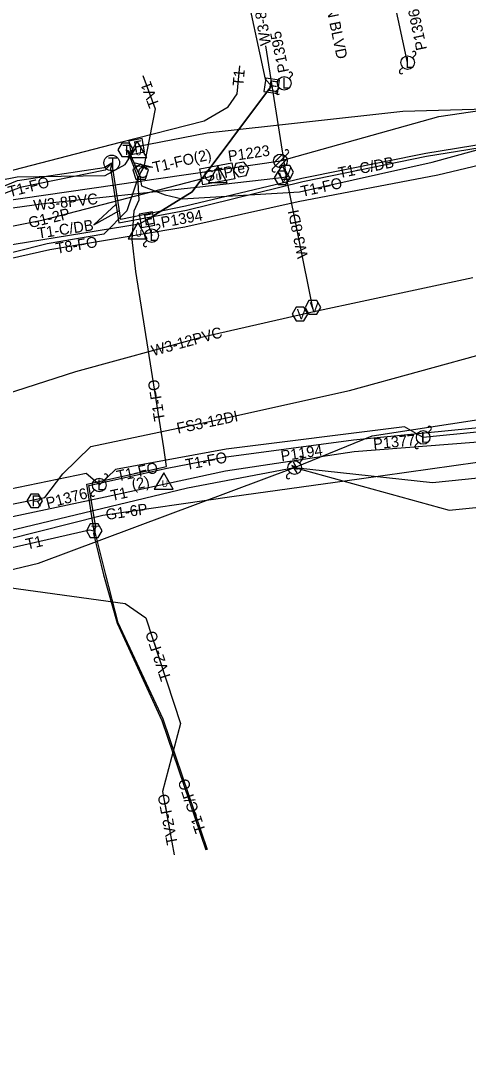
# Model space of a CAD drawing. Extents: x 2336688 to 2352634, y 362473 to 369571.
# Drawn here: x 2351731.6 to 2351896.3, y 368636.2 to 369013.7 of the extents above; entities that cross this region are included whole.
import ezdxf

# ---------------------------------------------------------------- set-up
doc = ezdxf.new("R2010")
doc.units = 0
for name, color, linetype in [('RD_EX_DV_TX_Prop', 7, 'Continuous'), ('RD_EX_RW', 7, 'Continuous'), ('RD_EX_RW_TX', 7, 'Continuous'), ('RD_HC_CL_Rel', 7, 'Continuous'), ('RD_HC_Data_Tic', 7, 'Continuous'), ('RD_PD_CstnLmt', 7, 'Continuous'), ('RD_PD_Final_TrvlWay', 7, 'Continuous'), ('RD_PD_PatLn2', 7, 'Continuous'), ('RD_PD_PatLn3', 7, 'Continuous'), ('RD_SHT_ShtClip', 7, 'Continuous'), ('RD_Sketch1', 7, 'Continuous'), ('RD_Sketch2', 7, 'Continuous'), ('RD_Sketch5', 7, 'Continuous'), ('RD_TX_Misc1', 7, 'Continuous')]:
    doc.layers.add(name, color=color, linetype=linetype)

msp = doc.modelspace()

# ---------------------------------------------------------------- linework, layer by layer
at = {"layer": 'RD_EX_RW'}
for p, q in [((2351780.21, 368959.6), (2351773.09, 368960.29)), ((2351780.21, 368959.6), (2351773.27, 368961.33)), ((2351758.51, 368938.6), (2351766.67, 368946.17)), ((2351758.47, 368938.59), (2351767.94, 368943.79))]:
    msp.add_line(p, q, dxfattribs=at)
at = {"layer": 'RD_EX_RW_TX'}
for points in [[(2351674.66, 368979.28), (2351676.95, 368964.93), (2351681.61, 368946.8), (2351685.81, 368947.48), (2351730.37, 368956.23), (2351762.74, 368956.69), (2351770.03, 368960.75), (2351774.28, 368967.37), (2351800.15, 368972.4), (2351872.17, 368980.36), (2351937.74, 368982.19), (2351987.22, 368989.17), (2352041.91, 368999.4), (2352065.6, 369002.37), (2352089.73, 369004.61), (2352102.55, 369007.6), (2352102.58, 369015.62), (2352100.79, 369043.46)], [(2352338.07, 368997.32), (2352288.54, 369002.61), (2352238.52, 369006.32), (2352188.44, 369009.03), (2352146.1, 369006.66), (2352112.83, 369007.85), (2352101.04, 369009.02), (2352100.18, 369013.02), (2352099.24, 369013.18), (2352099.24, 369013.18), (2352097.56, 369004.44), (2352066.15, 368999.94), (2352042.65, 368996), (2351987.9, 368984.55), (2351939.24, 368974.38), (2351880.64, 368964.81), (2351835.05, 368955.54), (2351792.2, 368945.42), (2351768.45, 368940.51), (2351765.56, 368959.31), (2351765.09, 368961.33)], [(2351441.13, 368877.68), (2351493.72, 368892.16), (2351542.92, 368904.09), (2351587.97, 368921.36), (2351612.24, 368928.51), (2351643.03, 368939.04), (2351685.22, 368949.09), (2351729.04, 368958.84), (2351768.34, 368969.01), (2351799.1, 368976.84), (2351807.9, 368981.96), (2351811.24, 368986.71), (2351812.17, 368997.01)], [(2351776.48, 368993.53), (2351781.05, 368981.28), (2351776.85, 368959.84), (2351775.71, 368957.81), (2351774.05, 368953.89), (2351770.61, 368943.72), (2351762.16, 368935.08), (2351741.35, 368931.51), (2351693.7, 368919.57), (2351644.17, 368909.19), (2351595.95, 368896.32), (2351580.02, 368891.2), (2351548.35, 368884.52), (2351499.06, 368872), (2351450.2, 368859.78)], [(2351758.66, 368825.96), (2351758.44, 368827.26), (2351755.96, 368843.15), (2351785.24, 368849.63), (2351784.29, 368856.52), (2351773.91, 368921.34), (2351772.63, 368933.13), (2351773.4, 368943.66), (2351775.18, 368947.68), (2351774.66, 368956.23), (2351771, 368965.69), (2351770.23, 368966.13), (2351771.27, 368965.86), (2351775.42, 368956.47), (2351776.04, 368952.93), (2351784.75, 368949.58), (2351790.96, 368948.12), (2351834.08, 368950.74), (2351882.96, 368961.6), (2351938.79, 368976.9)], [(2351450, 368860.64), (2351498.06, 368873.82), (2351548.09, 368885.57), (2351595.68, 368897.58), (2351616.34, 368903.53), (2351642.63, 368914.43), (2351689.81, 368938.15), (2351730.46, 368954.84), (2351762.28, 368959.7), (2351765.09, 368961.33), (2351764.64, 368959.22), (2351767.74, 368939.28), (2351792.58, 368943.98), (2351835.36, 368954.52), (2351880.81, 368963.77), (2351939.3, 368973.2)], [(2351026.67, 368705.73), (2351072.69, 368726.31), (2351095.34, 368740.06), (2351116.22, 368749.97), (2351165.51, 368767.17), (2351212.21, 368781.21), (2351311.35, 368807.4), (2351356.55, 368822.99), (2351403.13, 368840.09), (2351451.54, 368852.43), (2351499.93, 368866.02), (2351548.68, 368876.43), (2351597.38, 368889.51), (2351644.05, 368904.92), (2351693.91, 368918.56), (2351742.3, 368929.46), (2351791.99, 368937.8), (2351833.59, 368947.12), (2351885, 368956.88), (2351939.56, 368969.89)], [(2351765.09, 368961.33), (2351762.65, 368958.7), (2351731.46, 368952.33), (2351690.92, 368936.8), (2351644.39, 368912.81), (2351617.15, 368901.31), (2351597.28, 368893.86), (2351548.04, 368883.26), (2351498.82, 368871.39), (2351450.63, 368858.65), (2351402.34, 368844.85), (2351353.62, 368832.17), (2351306.23, 368821.59), (2351280.49, 368815.25), (2351211.24, 368794.97), (2351186.06, 368787.7), (2351186.43, 368794.28), (2351186.89, 368796.09), (2351185.08, 368794.48), (2351153.67, 368786.02), (2351107.67, 368770.53), (2351057.77, 368748.3), (2351012.48, 368735.27)], [(2351800.26, 368708.59), (2351783.98, 368756.59), (2351767.48, 368792.11), (2351762.88, 368809.69), (2351759.04, 368825.42), (2351758.66, 368825.96), (2351759.26, 368827.23), (2351756.66, 368842.63), (2351785.44, 368848.99), (2351806.34, 368852.99), (2351854.03, 368859.38), (2351906.18, 368864.55), (2351953.78, 368869.16), (2351999.38, 368874.93), (2352002.29, 368863.43), (2352001.55, 368861.67), (2352003.47, 368859.64), (2352009.35, 368840.16), (2352015.45, 368822.2), (2352011.56, 368815.85), (2352019.33, 368768.13), (2352023.49, 368743.71)], [(2351356.36, 368718.44), (2351351.37, 368734.97), (2351351.07, 368736.27), (2351352.08, 368735.83), (2351354.55, 368734.64), (2351363.44, 368738.12), (2351379.73, 368744.54), (2351398.33, 368751.76), (2351424.73, 368759.16), (2351470.85, 368771.57), (2351519.59, 368782.94), (2351559.62, 368792.7), (2351576.11, 368797.45), (2351601.1, 368804.55), (2351618.26, 368808.83), (2351664.35, 368818.5), (2351712.26, 368827.78), (2351760.99, 368838.04), (2351806.87, 368848.05), (2351854.2, 368855.12), (2351907.65, 368859.27)], [(2351469.79, 368774.45), (2351518.56, 368788.63), (2351559.06, 368797.29), (2351582.72, 368800.31), (2351584.07, 368794.92), (2351586.12, 368789.37), (2351586.25, 368788.52), (2351587.94, 368791.42), (2351594.9, 368792.63), (2351620.36, 368798.87), (2351634.16, 368804.06), (2351665.64, 368810.12), (2351714.33, 368816.59), (2351756.9, 368826.27), (2351758.66, 368825.96), (2351758.35, 368824.95), (2351762.12, 368809.74), (2351767.08, 368791.96), (2351783.55, 368756.14), (2351799.72, 368708.59)], [(2351637.62, 368802.44), (2351638.61, 368802.8), (2351648.75, 368802.95), (2351666.69, 368806.19), (2351717.35, 368806.44), (2351770.06, 368799.18), (2351777.6, 368793.92), (2351790.36, 368754.99), (2351783.74, 368729.96), (2351788.08, 368706.76)]]:
    msp.add_lwpolyline(points, dxfattribs=at)
for points in [[(2351773.12, 368966.13), (2351771.67, 368968.63), (2351768.79, 368968.63), (2351767.34, 368966.13), (2351768.79, 368963.63), (2351771.67, 368963.63)], [(2351776.29, 368970.28), (2351771.37, 368969.38), (2351772.27, 368964.46), (2351777.19, 368965.36)], [(2351775.71, 368960.81), (2351772.86, 368958.73), (2351773.95, 368955.38), (2351777.48, 368955.38), (2351778.57, 368958.73)], [(2351761.54, 368825.96), (2351760.1, 368828.46), (2351757.21, 368828.46), (2351755.77, 368825.96), (2351757.21, 368823.46), (2351760.1, 368823.46)]]:
    msp.add_lwpolyline(points, close=True, dxfattribs=at)
msp.add_circle((2351765.09, 368961.33), 2.89, dxfattribs=at)
at = {"layer": 'RD_HC_CL_Rel'}
for points in [[(2351211.87, 369060.2), (2351223.48, 369007.05), (2351235.68, 368951.97), (2351248.3, 368899.28), (2351256.86, 368864.38), (2351258.4, 368860.79), (2351267.06, 368853.06), (2351279.19, 368842.1), (2351287.59, 368836.67), (2351300.9, 368835.62), (2351301.79, 368834.14), (2351303.04, 368833.64), (2351320.88, 368837.27), (2351336.77, 368841.59), (2351351.45, 368846.05), (2351396.57, 368859.65), (2351447.03, 368875.53), (2351494.07, 368886.58), (2351543.46, 368901.18), (2351588.65, 368910.33), (2351641.69, 368920.56), (2351691.88, 368930.79), (2351740.06, 368940.33), (2351801.74, 368956.51)], [(2351470.14, 368766.16), (2351521.03, 368777.02), (2351560.63, 368787.9), (2351594.48, 368794.14), (2351619.97, 368801.96), (2351648.53, 368809.83), (2351665.14, 368813.04), (2351714.69, 368819.75), (2351761.78, 368831.73), (2351809.21, 368838.57), (2351856.12, 368845.07), (2351908.31, 368852.47)]]:
    msp.add_lwpolyline(points, dxfattribs=at)
for points in [[(2351810.38, 368955.41), (2351798.58, 368953.2), (2351797.48, 368959.1), (2351809.27, 368961.31)], [(2351815.5, 368959.42), (2351813.62, 368961.61), (2351810.78, 368961.08), (2351809.83, 368958.36), (2351811.7, 368956.17), (2351814.54, 368956.7)]]:
    msp.add_lwpolyline(points, close=True, dxfattribs=at)
at = {"layer": 'RD_HC_Data_Tic'}
for p, q in [((2351875.67, 369000), (2351876.74, 369001.06)), ((2351871.08, 368995.41), (2351872.14, 368996.47)), ((2351830.29, 368992.39), (2351831.35, 368993.46)), ((2351825.69, 368987.8), (2351826.75, 368988.86)), ((2351824.7, 368961.41), (2351827.76, 368964.47)), ((2351825.35, 368960.29), (2351828.88, 368963.82)), ((2351828.88, 368963.82), (2351829.95, 368964.88)), ((2351824.29, 368959.23), (2351825.35, 368960.29)), ((2351826.47, 368959.64), (2351829.53, 368962.7)), ((2351781.57, 368936.33), (2351782.63, 368937.39)), ((2351776.97, 368931.74), (2351778.03, 368932.8)), ((2351881.38, 368862.06), (2351882.44, 368863.12)), ((2351876.78, 368857.47), (2351877.84, 368858.53)), ((2351834.12, 368850.99), (2351835.18, 368852.05)), ((2351829.52, 368846.4), (2351830.58, 368847.46)), ((2351762.27, 368844.56), (2351763.33, 368845.62)), ((2351757.67, 368839.96), (2351758.73, 368841.02))]:
    msp.add_line(p, q, dxfattribs=at)
msp.add_lwpolyline([(2351831.96, 368851.23), (2351832.78, 368849.22), (2351831.33, 368850.02), (2351833.2, 368847.34), (2351833.2, 368847.34), (2351832, 368849.43), (2351833.38, 368848.63)], close=True, dxfattribs=at)
for centre in [(2351873.91, 368998.24), (2351828.52, 368990.63), (2351827.12, 368962.06), (2351779.8, 368934.57), (2351879.61, 368860.3), (2351832.35, 368849.22), (2351760.5, 368842.79)]:
    msp.add_circle(centre, 2.5, dxfattribs=at)
for centre, start, end in [((2351876.21, 369001.59), 315, 135), ((2351830.82, 368993.99), 315, 135), ((2351871.61, 368994.88), 135, 315), ((2351826.22, 368987.27), 135, 315), ((2351829.42, 368965.41), 315, 135), ((2351824.82, 368958.7), 135, 315), ((2351782.1, 368937.92), 315, 135), ((2351777.5, 368931.21), 135, 315), ((2351881.91, 368863.65), 315, 135), ((2351877.31, 368856.94), 135, 315), ((2351834.65, 368852.58), 315, 135), ((2351762.8, 368846.15), 315, 135), ((2351830.05, 368845.87), 135, 315), ((2351758.2, 368839.43), 135, 315)]:
    msp.add_arc(centre, 0.75, start, end, dxfattribs=at)
at = {"layer": 'RD_PD_Final_TrvlWay'}
for p, q in [((2351873.91, 368998.24), (2351857.57, 369073.04)), ((2351778.05, 368940.44), (2351779.8, 368934.57))]:
    msp.add_line(p, q, dxfattribs=at)
for points in [[(2351813.53, 369029.36), (2351821.49, 368992.14), (2351823.9, 368989.67), (2351794.62, 368950.67), (2351778.05, 368940.44), (2351775.15, 368938.78), (2351642.49, 368917.24), (2351514.5, 368883.56), (2351514.77, 368877.23), (2351511.62, 368882.8), (2351407.12, 368855.31), (2351405.59, 368848.58), (2351402.3, 368851.72), (2351332.34, 368833.32), (2351331.07, 368827.87)], [(2351778.05, 368940.44), (2351794.62, 368950.67), (2351823.9, 368989.67)], [(2351962.19, 368868.54), (2351879.61, 368860.3), (2351872.73, 368864.24), (2351807.16, 368856.02), (2351766.5, 368848.48), (2351760.54, 368842.85), (2351755.71, 368847.01), (2351656.05, 368826.47), (2351653.74, 368820.38), (2351649.2, 368824.53), (2351583.65, 368809.05), (2351587.65, 368792.13), (2351587.61, 368789.27), (2351586.29, 368791.8), (2351582.29, 368808.73), (2351542.35, 368799.3), (2351537.51, 368798.37), (2351536.49, 368793.38), (2351533.02, 368797.4), (2351459.1, 368778.67), (2351456.43, 368773.13), (2351451.34, 368775.83), (2351353, 368749.17), (2351345.06, 368741.32)]]:
    msp.add_lwpolyline(points, dxfattribs=at)
for points in [[(2351826.74, 368991.78), (2351821.8, 368992.51), (2351821.06, 368987.57), (2351826.01, 368986.83)], [(2351780.05, 368943.35), (2351775.14, 368942.44), (2351776.05, 368937.53), (2351780.96, 368938.44)]]:
    msp.add_lwpolyline(points, close=True, dxfattribs=at)
at = {"layer": 'RD_PD_PatLn3'}
for points in [[(2351774.5, 368969.36), (2351771.04, 368963.36), (2351777.97, 368963.36)], [(2351804.1, 368960.17), (2351800.64, 368954.17), (2351807.57, 368954.17)], [(2351774.64, 368939.41), (2351771.18, 368933.41), (2351778.11, 368933.41)], [(2351784.23, 368847.28), (2351780.76, 368841.28), (2351787.69, 368841.28)]]:
    msp.add_lwpolyline(points, close=True, dxfattribs=at)
at = {"layer": 'RD_SHT_ShtClip'}
msp.add_line((2351572.13, 368925.03), (2351827.12, 368962.06), dxfattribs=at)
for points in [[(2351827.12, 368962.06), (2351885.36, 368978.36), (2352011.84, 368996.99), (2352072.58, 368998.19)], [(2351832.35, 368849.22), (2351860.91, 368860.88), (2352060.94, 368891.58), (2352091.68, 368889.02)], [(2351832.35, 368849.22), (2351889.18, 368833.54), (2352180.82, 368862.57), (2352233.45, 368889.14)], [(2351832.35, 368849.22), (2351883.04, 368843.68), (2352056.96, 368861.54), (2352105.46, 368877.27)], [(2351439.98, 368755.4), (2351540.29, 368766.59), (2351738.13, 368814.04), (2351832.35, 368849.22)], [(2351637.62, 368802.44), (2351676.06, 368813.68), (2351793, 368841.77), (2351832.35, 368849.22)]]:
    msp.add_lwpolyline(points, dxfattribs=at)
at = {"layer": 'RD_Sketch2'}
for points in [[(2351839.37, 368906.5), (2351838.84, 368909.14), (2351829.3, 368956.12), (2351829.09, 368957.89), (2351821.73, 369004.47)], [(2351829.3, 368956.12), (2351825.48, 368955.65), (2351796.45, 368952.27), (2351741.12, 368946.36), (2351687.12, 368939), (2351639.33, 368929.45), (2351588.67, 368920.67), (2351539, 368909.06), (2351489.27, 368896.27), (2351440.12, 368880.97), (2351434.75, 368879.34), (2351397.29, 368866.24), (2351394.12, 368865.24), (2351393.38, 368867.94), (2351392.71, 368869.71)], [(2351897.87, 368918.99), (2351839.37, 368906.5), (2351797.47, 368896.96), (2351751.8, 368884.48), (2351707.52, 368870.2), (2351656.24, 368856.32), (2351608.11, 368843.77), (2351558.65, 368832.09), (2351508.67, 368819.53), (2351459.49, 368806.33), (2351412.81, 368793.12), (2351368.32, 368777.82), (2351320.48, 368761.6), (2351291.49, 368752.07), (2351283.21, 368749.13), (2351230.34, 368719.64), (2351184.82, 368699.7), (2351136.28, 368683.67), (2351113.69, 368676.51), (2351093.58, 368668.35), (2351042.86, 368655.18), (2350995.25, 368636.19)]]:
    msp.add_lwpolyline(points, dxfattribs=at)
for points in [[(2351831.98, 368957.89), (2351830.53, 368960.39), (2351827.65, 368960.39), (2351826.2, 368957.89), (2351827.65, 368955.39), (2351830.53, 368955.39)], [(2351830.61, 368955.85), (2351829.17, 368958.35), (2351826.28, 368958.35), (2351824.84, 368955.85), (2351826.28, 368953.35), (2351829.17, 368953.35)], [(2351841.96, 368908.17), (2351840.52, 368910.67), (2351837.63, 368910.67), (2351836.19, 368908.17), (2351837.63, 368905.67), (2351840.52, 368905.67)], [(2351837.21, 368905.69), (2351835.77, 368908.19), (2351832.88, 368908.19), (2351831.44, 368905.69), (2351832.88, 368903.19), (2351835.77, 368903.19)]]:
    msp.add_lwpolyline(points, close=True, dxfattribs=at)
at = {"layer": 'RD_Sketch5'}
msp.add_lwpolyline([(2351470.05, 368773.88), (2351518.77, 368787.72), (2351559.13, 368796.23), (2351617.79, 368811.57), (2351663.83, 368820.09), (2351711.27, 368832.32), (2351740.53, 368838.18), (2351747.1, 368846.93), (2351757.38, 368857), (2351803.33, 368866.61), (2351852.53, 368877.54), (2351904.23, 368891.75)], dxfattribs=at)
msp.add_lwpolyline([(2351739.67, 368836.98), (2351738.22, 368839.48), (2351735.34, 368839.48), (2351733.89, 368836.98), (2351735.34, 368834.47), (2351738.22, 368834.47)], close=True, dxfattribs=at)

# ---------------------------------------------------------------- texts
at = {"layer": 'RD_EX_DV_TX_Prop'}
for s, rotation, p in [('P1396', 101.6792, (2351881.04, 369003.19)), ('P1395', 101.6792, (2351830.31, 368994.96)), ('P1223', 8.2617, (2351808.15, 368961.8)), ('P1394', 10.334, (2351783.56, 368937.44)), ('P1377', 5.6602, (2351861.45, 368855.9)), ('P1194', 8.4903, (2351827.55, 368851.47)), ('P1376', 14.3887, (2351741.49, 368834.13))]:
    msp.add_text(s, height=4, rotation=rotation, dxfattribs=at).set_placement(p)
at = {"layer": 'RD_EX_RW'}
for s, rotation, p in [('T1', 84.8472, (2351813.49, 368989.4)), ('TV1', 110.4499, (2351782.72, 368982.52)), ('T1-FO(2)', 13.1603, (2351780.67, 368957.66)), ('T1-C/DB', 11.4971, (2351848.8, 368955.65)), ('T1-FO', 14.5402, (2351727.53, 368948.67)), ('T1-FO', 12.5252, (2351835.1, 368948.81)), ('T1-C/DB', 8.7436, (2351738.08, 368933.43)), ('T8-FO', 9.5373, (2351744.87, 368927.86)), ('T1-FO', 99.0986, (2351784.7, 368866.63)), ('T1-FO', 10.5947, (2351792.58, 368848.32)), ('T1-FO', 12.4764, (2351767.36, 368844.06)), ('(2)', 12.4764, (2351772.91, 368840.9)), ('T1', 12.3146, (2351765.13, 368836.89)), ('T1', 12.81, (2351733.96, 368819)), ('TV2-FO', 108.1342, (2351787.06, 368771.48)), ('T1-C/FO', 108.7769, (2351799.76, 368715.49)), ('TV2-FO', 100.5767, (2351789.37, 368710.73))]:
    msp.add_text(s, height=4, rotation=rotation, dxfattribs=at).set_placement(p)
at = {"layer": 'RD_EX_RW_TX'}
for height, p in [(3.75, (2351769.02, 368964.26)), (4.12, (2351763.76, 368959.27)), (3.75, (2351757.45, 368824.08))]:
    msp.add_text('T', height=height, dxfattribs=at).set_placement(p)
for s, rotation, p in [('F', 10.334, (2351773.52, 368965.2)), ('C', 360, (2351774.49, 368955.81))]:
    msp.add_text(s, height=4, rotation=rotation, dxfattribs=at).set_placement(p)
at = {"layer": 'RD_HC_CL_Rel'}
for s, height, p in [('GTP', 4, (2351799.31, 368954.35)), ('e', 3.75, (2351811.62, 368957.27))]:
    msp.add_text(s, height=height, rotation=10.6138, dxfattribs=at).set_placement(p)
at = {"layer": 'RD_HC_Data_Tic'}
for p in [(2351873.1, 368996.3), (2351827.71, 368988.69), (2351778.99, 368932.63), (2351878.8, 368858.36), (2351759.69, 368840.85)]:
    msp.add_text('L', height=4, rotation=360, dxfattribs=at).set_placement(p)
at = {"layer": 'RD_PD_CstnLmt'}
for s, rotation, p in [('W3-8PVC', 98.9821, (2351823.7, 369004.82)), ('W3-8PVC', 6.0985, (2351736.52, 368943.71)), ('W3-8DI', 101.4829, (2351837.32, 368926.65)), ('W3-12PVC', 15.2791, (2351780.28, 368890.19))]:
    msp.add_text(s, height=4, rotation=rotation, dxfattribs=at).set_placement(p)
at = {"layer": 'RD_PD_Final_TrvlWay'}
for rotation, p in [(351.5521, (2351822.41, 368987.87)), (10.5082, (2351777.22, 368938.25))]:
    msp.add_text('E', height=4, rotation=rotation, dxfattribs=at).set_placement(p)
at = {"layer": 'RD_PD_PatLn2'}
for s, rotation, p in [('G1-2P', 13.4355, (2351735, 368937.3)), ('G1-6P', 8.2108, (2351763.19, 368829.91))]:
    msp.add_text(s, height=4, rotation=rotation, dxfattribs=at).set_placement(p)
at = {"layer": 'RD_PD_PatLn3'}
for p in [(2351773.75, 368964.16), (2351803.35, 368954.97), (2351773.89, 368934.21), (2351783.47, 368842.08)]:
    msp.add_text('U', height=2.4, dxfattribs=at).set_placement(p)
at = {"layer": 'RD_Sketch1'}
msp.add_text('FS3-12DI', height=4, rotation=11.8054, dxfattribs=at).set_placement((2351789.43, 368861.66))
at = {"layer": 'RD_Sketch2'}
for p in [(2351827.88, 368956.02), (2351826.51, 368953.98), (2351833.12, 368903.81), (2351837.86, 368906.3)]:
    msp.add_text('V', height=3.75, dxfattribs=at).set_placement(p)
at = {"layer": 'RD_Sketch5'}
msp.add_text('R', height=4, dxfattribs=at).set_placement((2351735.55, 368834.98))
at = {"layer": 'RD_TX_Misc1'}
msp.add_text('BELLE STATION BLVD', height=4, rotation=281.7285, dxfattribs=at).set_placement((2351836.4, 369054.85))

doc.saveas('drawing.dxf')
